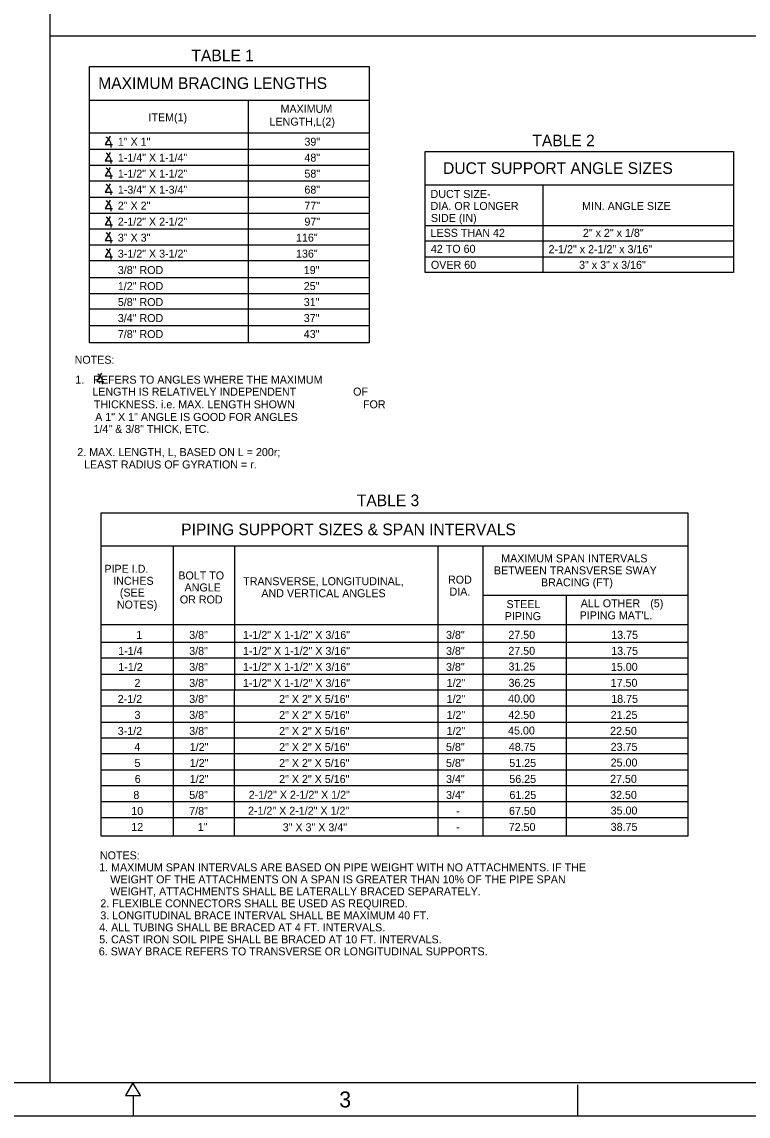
# Model space of a CAD drawing. Extents: x 9999.96 to 10005.26, y 9999.88 to 10002.38.
# Drawn here: x 10001.613 to 10002.521, y 9999.885 to 10001.252 of the extents above; entities that cross this region are included whole.
import ezdxf

# ---------------------------------------------------------------- set-up
doc = ezdxf.new("R2010")
doc.units = 0
doc.layers.add('Level 1', color=7, linetype='Continuous')
doc.layers.add('Level 2', color=7, linetype='Continuous')

msp = doc.modelspace()

# ---------------------------------------------------------------- linework, layer by layer
at = {"layer": 'Level 1'}
for p, q in [((10003.4187, 9999.9262), (10000.127, 9999.9262)), ((10001.752, 9999.9262), (10001.7428, 9999.9102)), ((10001.7613, 9999.9102), (10001.752, 9999.9262)), ((10002.3079, 9999.8845), (10002.3079, 9999.9235)), ((10001.7428, 9999.9102), (10001.7613, 9999.9102)), ((10001.7524, 9999.9102), (10001.7524, 9999.8845)), ((10003.4603, 9999.8845), (9999.9603, 9999.8845))]:
    msp.add_line(p, q, dxfattribs=at)
at = {"layer": 'Level 2'}
for p, q in [((10001.6482, 10002.3429), (10001.6482, 9999.9262)), ((10001.6482, 10001.2346), (10003.4187, 10001.2346)), ((10001.6976, 10001.1962), (10002.0471, 10001.1962)), ((10001.6976, 10000.8508), (10001.6976, 10001.1962)), ((10002.0471, 10001.1962), (10002.0471, 10000.8508)), ((10001.6979, 10001.1544), (10002.0471, 10001.1544)), ((10001.8961, 10001.1544), (10001.8961, 10000.8508)), ((10001.6979, 10001.1133), (10002.0471, 10001.1133)), ((10001.7234, 10001.1091), (10001.7173, 10001.0987)), ((10001.6978, 10001.0929), (10002.0471, 10001.0929)), ((10001.7173, 10001.0987), (10001.7263, 10001.0987)), ((10001.7234, 10001.0888), (10001.7173, 10001.0783)), ((10001.7173, 10001.0783), (10001.7263, 10001.0783)), ((10001.6978, 10001.0728), (10002.0471, 10001.0728)), ((10001.7234, 10001.0699), (10001.7173, 10001.0595)), ((10001.7173, 10001.0595), (10001.7263, 10001.0595)), ((10001.6978, 10001.0532), (10002.0471, 10001.0532)), ((10001.7234, 10001.0496), (10001.7173, 10001.0391)), ((10002.1173, 10001.0485), (10002.5026, 10001.0485)), ((10002.2644, 10001.0485), (10002.2644, 10000.9388)), ((10001.6978, 10001.0331), (10002.0471, 10001.0331)), ((10001.7173, 10001.0391), (10001.7263, 10001.0391)), ((10001.7234, 10001.0293), (10001.7173, 10001.0188)), ((10001.7173, 10001.0188), (10001.7263, 10001.0188)), ((10001.6978, 10001.0131), (10002.0471, 10001.0131)), ((10001.7234, 10001.0089), (10001.7173, 10000.9984)), ((10001.6978, 10000.9934), (10002.0471, 10000.9934)), ((10001.7173, 10000.9984), (10001.7263, 10000.9984)), ((10002.1173, 10000.9976), (10002.5026, 10000.9976)), ((10001.7234, 10000.9893), (10001.7173, 10000.9788)), ((10001.7173, 10000.9788), (10001.7263, 10000.9788)), ((10002.1173, 10000.9784), (10002.5026, 10000.9784)), ((10001.6978, 10000.9733), (10002.0471, 10000.9733)), ((10001.7234, 10000.969), (10001.7173, 10000.9585)), ((10001.6978, 10000.9537), (10002.0471, 10000.9537)), ((10001.7173, 10000.9585), (10001.7263, 10000.9585)), ((10002.1173, 10000.9586), (10002.5026, 10000.9586)), ((10001.6981, 10000.9327), (10002.0471, 10000.9327)), ((10001.6981, 10000.9124), (10002.0471, 10000.9124)), ((10001.6978, 10000.8933), (10002.0471, 10000.8933)), ((10001.6981, 10000.8727), (10002.0471, 10000.8727)), ((10002.0471, 10000.8508), (10001.6976, 10000.8508)), ((10001.7128, 10000.813), (10001.7068, 10000.8025)), ((10001.7068, 10000.8025), (10001.7157, 10000.8025)), ((10001.7121, 10000.6386), (10002.4457, 10000.6386)), ((10001.7121, 10000.2345), (10001.7121, 10000.6386)), ((10002.4457, 10000.6386), (10002.4457, 10000.2345)), ((10002.4457, 10000.5968), (10001.7121, 10000.5968)), ((10001.8023, 10000.5968), (10001.8023, 10000.2342)), ((10001.8788, 10000.5968), (10001.8787, 10000.2342)), ((10002.1329, 10000.5968), (10002.1329, 10000.2342)), ((10002.1894, 10000.5968), (10002.1894, 10000.2345)), ((10002.1897, 10000.5355), (10002.4457, 10000.5355)), ((10002.2936, 10000.5355), (10002.2936, 10000.2345)), ((10001.7121, 10000.4988), (10002.4457, 10000.4988)), ((10001.7121, 10000.4769), (10002.4457, 10000.4769)), ((10001.7121, 10000.4571), (10002.4457, 10000.4571)), ((10001.7121, 10000.437), (10002.4457, 10000.437)), ((10001.7121, 10000.4172), (10002.4457, 10000.4172)), ((10001.7121, 10000.3972), (10002.4457, 10000.3972)), ((10001.7121, 10000.3768), (10002.4457, 10000.3768)), ((10001.7121, 10000.3573), (10002.4457, 10000.3573)), ((10001.7121, 10000.3375), (10002.4457, 10000.3375)), ((10001.7121, 10000.3172), (10002.4457, 10000.3172)), ((10001.7121, 10000.2979), (10002.4457, 10000.2979)), ((10001.7121, 10000.2777), (10002.4457, 10000.2777)), ((10001.7121, 10000.2575), (10002.4457, 10000.2575)), ((10002.4457, 10000.2345), (10001.7121, 10000.2345))]:
    msp.add_line(p, q, dxfattribs=at)
msp.add_lwpolyline([(10002.1173, 10000.9388), (10002.1173, 10001.09), (10002.5026, 10001.09), (10002.5026, 10000.9388)], close=True, dxfattribs=at)
for centre in [(10001.7119, 10001.0971), (10001.7119, 10001.0768), (10001.7119, 10001.058), (10001.7119, 10001.0376), (10001.7119, 10001.0173), (10001.7119, 10000.9969), (10001.7119, 10000.9773), (10001.7119, 10000.957), (10001.7013, 10000.801)]:
    msp.add_arc(centre, 0.0129, 351.5535, 59.0793, dxfattribs=at)

# ---------------------------------------------------------------- texts
at = {"layer": 'Level 1'}
msp.add_text('3', height=0.02, dxfattribs=at).set_placement((10002.0098, 9999.8953))
at = {"layer": 'Level 2'}
for s, height, p in [('TABLE 1', 0.01458, (10001.8251, 10001.2028)), ('MAXIMUM BRACING LENGTHS', 0.014583, (10001.7086, 10001.1682)), ('MAXIMUM', 0.01, (10001.9365, 10001.1384)), ('ITEM(1)', 0.01, (10001.7714, 10001.1278)), ('LENGTH,L(2)', 0.01, (10001.9227, 10001.1224)), ('1" X 1"', 0.01, (10001.7331, 10001.0973)), ('39"', 0.01, (10001.9663, 10001.0973)), ('TABLE 2', 0.01458, (10002.2512, 10001.0965)), ('1-1/4" X 1-1/4"', 0.01, (10001.7331, 10001.0774)), ('48"', 0.01, (10001.9663, 10001.0774)), ('DUCT SUPPORT ANGLE SIZES', 0.014583, (10002.1396, 10001.062)), ('1-1/2" X 1-1/2"', 0.01, (10001.7331, 10001.0574)), ('58"', 0.01, (10001.9663, 10001.0574)), ('1-3/4" X 1-3/4"', 0.01, (10001.7331, 10001.0374)), ('68"', 0.01, (10001.9663, 10001.0374)), ('DUCT SIZE-', 0.01, (10002.124, 10001.032)), ('2" X 2"', 0.01, (10001.7331, 10001.0174)), ('77"', 0.01, (10001.9663, 10001.0174)), ('DIA. OR LONGER', 0.01, (10002.124, 10001.017)), ('MIN. ANGLE SIZE', 0.01, (10002.3134, 10001.0169)), ('2-1/2" X 2-1/2"', 0.01, (10001.7331, 10000.9974)), ('97"', 0.01, (10001.9663, 10000.9974)), ('SIDE (IN)', 0.01, (10002.1244, 10001.002)), ('LESS THAN 42', 0.01, (10002.124, 10000.9834)), ('2" x 2" x 1/8"', 0.01, (10002.3144, 10000.9834)), ('3" X 3"', 0.01, (10001.7331, 10000.9774)), ('116"', 0.01, (10001.9558, 10000.9774)), ('3-1/2" X 3-1/2"', 0.01, (10001.7331, 10000.9574)), ('136"', 0.01, (10001.9558, 10000.9574)), ('42 TO 60', 0.01, (10002.1244, 10000.9634)), ('2-1/2" x 2-1/2" x 3/16"', 0.01, (10002.2715, 10000.963)), ('OVER 60', 0.01, (10002.1244, 10000.9434)), ('3" x 3" x 3/16"', 0.01, (10002.3096, 10000.9434)), ('3/8" ROD', 0.01, (10001.7331, 10000.9369)), ('19"', 0.01, (10001.9655, 10000.9369)), ('1/2" ROD', 0.01, (10001.7331, 10000.9169)), ('25"', 0.01, (10001.9655, 10000.9169)), ('5/8" ROD', 0.01, (10001.7331, 10000.8969)), ('31"', 0.01, (10001.9655, 10000.8969)), ('3/4" ROD', 0.01, (10001.7331, 10000.8769)), ('37"', 0.01, (10001.9655, 10000.8769)), ('7/8" ROD', 0.01, (10001.7331, 10000.8569)), ('43"', 0.01, (10001.9655, 10000.8569)), ('NOTES:', 0.01, (10001.6791, 10000.8248)), ('1.   REFERS TO ANGLES WHERE THE MAXIMUM', 0.01, (10001.6799, 10000.7999)), ('LENGTH IS RELATIVELY INDEPENDENT', 0.01, (10001.7012, 10000.7849)), ('OF', 0.01, (10002.0272, 10000.785)), ('THICKNESS. i.e. MAX. LENGTH SHOWN', 0.01, (10001.7031, 10000.7691)), ('FOR', 0.01, (10002.0395, 10000.7691)), ('A 1" X 1" ANGLE IS GOOD FOR ANGLES', 0.01, (10001.7048, 10000.7533)), ('1/4" & 3/8" THICK, ETC.', 0.01, (10001.7027, 10000.7383)), ('2. MAX. LENGTH, L, BASED ON L = 200r; ', 0.01, (10001.6824, 10000.7094)), ('   LEAST RADIUS OF GYRATION = r.', 0.01, (10001.6797, 10000.6939)), ('TABLE 3', 0.01458, (10002.0318, 10000.6468)), ('PIPING SUPPORT SIZES & SPAN INTERVALS', 0.014583, (10001.8123, 10000.6105)), ('MAXIMUM SPAN INTERVALS', 0.01, (10002.2123, 10000.5766)), ('PIPE I.D.', 0.01, (10001.7163, 10000.5635)), ('BETWEEN TRANSVERSE SWAY', 0.01, (10002.2032, 10000.5616)), ('INCHES', 0.01, (10001.7273, 10000.5485)), ('BOLT TO', 0.01, (10001.8087, 10000.5552)), ('TRANSVERSE, LONGITUDINAL,', 0.01, (10001.8898, 10000.548)), ('ROD', 0.01, (10002.1458, 10000.55)), ('BRACING (FT)', 0.01, (10002.262, 10000.5466)), ('(SEE', 0.01, (10001.7356, 10000.5338)), ('ANGLE', 0.01, (10001.8165, 10000.5402)), ('AND VERTICAL ANGLES', 0.01, (10001.9125, 10000.533)), ('DIA.', 0.01, (10002.1477, 10000.535)), ('NOTES)', 0.01, (10001.7319, 10000.5188)), ('OR ROD', 0.01, (10001.8106, 10000.5252)), ('STEEL', 0.01, (10002.2189, 10000.5194)), ('ALL OTHER', 0.01, (10002.3117, 10000.5204)), ('(5)', 0.01, (10002.3986, 10000.5204)), ('PIPING', 0.01, (10002.2167, 10000.5044)), ("PIPING MAT'L.", 0.01, (10002.3103, 10000.5054)), ('1', 0.01, (10001.7561, 10000.4809)), ('3/8"', 0.01, (10001.8223, 10000.4809)), ('1-1/2" X 1-1/2" X 3/16"', 0.01, (10001.8894, 10000.4809)), ('3/8"', 0.01, (10002.1433, 10000.4809)), ('27.50', 0.01, (10002.2212, 10000.481)), ('13.75', 0.01, (10002.3498, 10000.481)), ('1-1/4', 0.01, (10001.7335, 10000.4609)), ('3/8"', 0.01, (10001.8223, 10000.4609)), ('1-1/2" X 1-1/2" X 3/16"', 0.01, (10001.8894, 10000.4609)), ('3/8"', 0.01, (10002.1433, 10000.4609)), ('27.50', 0.01, (10002.2212, 10000.461)), ('13.75', 0.01, (10002.3498, 10000.461)), ('1-1/2', 0.01, (10001.7337, 10000.4409)), ('3/8"', 0.01, (10001.8223, 10000.4409)), ('1-1/2" X 1-1/2" X 3/16"', 0.01, (10001.8894, 10000.4409)), ('3/8"', 0.01, (10002.1433, 10000.4409)), ('31.25', 0.01, (10002.2214, 10000.4414)), ('15.00', 0.01, (10002.3494, 10000.441)), ('2', 0.01, (10001.7539, 10000.4209)), ('3/8"', 0.01, (10001.8223, 10000.4209)), ('1-1/2" X 1-1/2" X 3/16"', 0.01, (10001.8894, 10000.4208)), ('1/2"', 0.01, (10002.144, 10000.4209)), ('36.25', 0.01, (10002.2214, 10000.421)), ('17.50', 0.01, (10002.3491, 10000.421)), ('2-1/2', 0.01, (10001.733, 10000.4009)), ('3/8"', 0.01, (10001.8223, 10000.4009)), ('2" X 2" X 5/16"', 0.01, (10001.9347, 10000.4008)), ('1/2"', 0.01, (10002.144, 10000.4009)), ('40.00', 0.01, (10002.221, 10000.4014)), ('18.75', 0.01, (10002.3498, 10000.401)), ('3', 0.01, (10001.7539, 10000.3809)), ('3/8"', 0.01, (10001.8223, 10000.3809)), ('2" X 2" X 5/16"', 0.01, (10001.9347, 10000.3808)), ('1/2"', 0.01, (10002.144, 10000.3809)), ('42.50', 0.01, (10002.2212, 10000.381)), ('21.25', 0.01, (10002.3491, 10000.381)), ('3-1/2', 0.01, (10001.733, 10000.3609)), ('3/8"', 0.01, (10001.8223, 10000.3609)), ('2" X 2" X 5/16"', 0.01, (10001.9347, 10000.3608)), ('1/2"', 0.01, (10002.144, 10000.3609)), ('45.00', 0.01, (10002.2209, 10000.3614)), ('22.50', 0.01, (10002.3484, 10000.361)), ('4', 0.01, (10001.7537, 10000.3409)), ('1/2"', 0.01, (10001.823, 10000.3409)), ('2" X 2" X 5/16"', 0.01, (10001.9347, 10000.3408)), ('5/8"', 0.01, (10002.1433, 10000.3409)), ('48.75', 0.01, (10002.2218, 10000.341)), ('23.75', 0.01, (10002.3491, 10000.341)), ('5', 0.01, (10001.7539, 10000.3209)), ('1/2"', 0.01, (10001.823, 10000.3209)), ('2" X 2" X 5/16"', 0.01, (10001.9347, 10000.3208)), ('5/8"', 0.01, (10002.1433, 10000.3209)), ('51.25', 0.01, (10002.2224, 10000.3209)), ('25.00', 0.01, (10002.3491, 10000.3214)), ('6', 0.01, (10001.7542, 10000.3009)), ('1/2"', 0.01, (10001.823, 10000.3009)), ('2" X 2" X 5/16"', 0.01, (10001.9347, 10000.3008)), ('3/4"', 0.01, (10002.1433, 10000.3009)), ('56.25', 0.01, (10002.2224, 10000.3009)), ('27.50', 0.01, (10002.3484, 10000.301)), ('8', 0.01, (10001.7525, 10000.2809)), ('5/8"', 0.01, (10001.8223, 10000.2809)), ('2-1/2" X 2-1/2" X 1/2"', 0.01, (10001.8966, 10000.2811)), ('3/4"', 0.01, (10002.1433, 10000.2809)), ('61.25', 0.01, (10002.2226, 10000.2809)), ('32.50', 0.01, (10002.3484, 10000.281)), ('10', 0.01, (10001.7499, 10000.2609)), ('7/8"', 0.01, (10001.8223, 10000.2609)), ('2-1/2" X 2-1/2" X 1/2"', 0.01, (10001.8958, 10000.2612)), ('67.50', 0.01, (10002.222, 10000.2609)), ('35.00', 0.01, (10002.3491, 10000.2614)), ('-', 0.01, (10002.1559, 10000.2609)), ('12', 0.01, (10001.7499, 10000.2409)), ('1"', 0.01, (10001.833, 10000.2409)), ('3" X 3" X 3/4"', 0.01, (10001.9392, 10000.2405)), ('-', 0.01, (10002.1559, 10000.2409)), ('72.50', 0.01, (10002.2217, 10000.2409)), ('38.75', 0.01, (10002.3491, 10000.241)), ('NOTES:', 0.01, (10001.7107, 10000.2054)), ('1. MAXIMUM SPAN INTERVALS ARE BASED ON PIPE WEIGHT WITH NO ATTACHMENTS. IF THE', 0.01, (10001.7098, 10000.1904)), ('   WEIGHT OF THE ATTACHMENTS ON A SPAN IS GREATER THAN 10% OF THE PIPE SPAN', 0.01, (10001.7126, 10000.1754)), ('   WEIGHT, ATTACHMENTS SHALL BE LATERALLY BRACED SEPARATELY.', 0.01, (10001.7126, 10000.1604)), ('2. FLEXIBLE CONNECTORS SHALL BE USED AS REQUIRED.', 0.01, (10001.7112, 10000.1454)), ('3. LONGITUDINAL BRACE INTERVAL SHALL BE MAXIMUM 40 FT.', 0.01, (10001.7112, 10000.1304)), ('4. ALL TUBING SHALL BE BRACED AT 4 FT. INTERVALS.', 0.01, (10001.7098, 10000.1154)), ('5. CAST IRON SOIL PIPE SHALL BE BRACED AT 10 FT. INTERVALS.', 0.01, (10001.7098, 10000.1004)), ('6. SWAY BRACE REFERS TO TRANSVERSE OR LONGITUDINAL SUPPORTS.', 0.01, (10001.7093, 10000.0854))]:
    msp.add_text(s, height=height, dxfattribs=at).set_placement(p)

doc.saveas('drawing.dxf')
